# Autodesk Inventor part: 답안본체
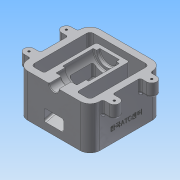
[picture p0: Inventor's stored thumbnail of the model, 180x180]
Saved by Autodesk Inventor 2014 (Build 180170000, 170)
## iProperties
Created: 2018-01
Part Number: 답안본체
Material: 알루미늄 6061
Document SubType Name: Modeling
Designer: NET
Density: 2.71 g/cm^3
Appearance: 알루미늄 - 평지
Mass: 998.903 g
Surface Area: 834.406 cm^2
Volume: 368.599 cm^3
Author: NET
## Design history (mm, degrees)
sketch "스케치1"
  geometry: L1 (55, -55)-(-55, -55); L2 (-55, -55)-(-55, 55); L3 (-55, 55)-(55, 55); L4 (55, 55)-(55, -55); L5 (55, -55)-(-55, 55); L6 (-55, -55)-(55, 55); 1 further point
  constraints: 12 end point, 2 midpoint, 2 parallel, 1 horizontal, 1 perpendicular
  dimensions: "d0" = 110 distance of L2.end L3.end; "d1" = 110 distance of L3.end L1.start
extrude "돌출1" new body sketch "스케치1" distance "d2" = 65; taper "d3" = 0 deg
sketch "스케치2"
  geometry: L1 (55, -55)-(55, 55) reference; L2 (55, 55)-(-55, 55) reference; L3 (45, -45)-(-45, -45); L4 (-45, -45)-(-45, 45); L5 (-45, 45)-(45, 45); L6 (45, 45)-(45, -45); L7 (45, -45)-(-45, 45); L8 (-45, -45)-(45, 45); 1 further point
  constraints: 12 end point, 2 midpoint, 2 parallel, 1 horizontal, 1 perpendicular
  dimensions: "d4" = 10 distance between parallel lines of L2 L5; "d5" = 10 distance between parallel lines of L1 L6
extrude "돌출2" cut sketch "스케치2" stored distance "d6" = 65; taper "d7" = 0 deg
sketch "스케치3"
  geometry: L1 (-55, -55)-(55, -55) reference; L2 (55, -55)-(55, 55) reference; L3 (-55, 55)-(-55, -55) reference; L4 (-65, -35.5)-(-55, -35.5); L5 (-65, -20.5)-(-55, -20.5); L6 (-65, 21.5)-(-55, 21.5); L7 (-65, 36.5)-(-55, 36.5); L8 (65, 36.5)-(55, 36.5); L9 (55, 55)-(55, -55) reference; L10 (65, 21.5)-(55, 21.5); L11 (65, -20.5)-(55, -20.5); L12 (65, -35.5)-(55, -35.5); A1 r 7.5 centre (-65, -28) between (-65, -20.5) and (-65, -35.5); A2 r 7.5 centre (-65, 29) between (-65, 36.5) and (-65, 21.5); A3 r 7.5 centre (65, -28) between (65, -35.5) and (65, -20.5); A4 r 7.5 centre (65, 29) between (65, 21.5) and (65, 36.5); 1 further point
  constraints: 16 end point, 8 point on circle, 8 point on line, 8 tangent, 6 perpendicular, 4 centre point, 3 equal radius, 2 parallel
  dimensions: "d8" = 57 distance of A2.centre A1.centre; "d9" = 27 distance from line of L1 A1.centre; "d10" = 27 distance from line of L1 A3.centre; "d11" = 57 distance of A4.centre A3.centre; "d12" = 10 distance from line of L2 A4.centre; "d13" = 10 distance from line of L2 A3.centre; "d14" = 15 diameter of A4; "d15" = 10 distance from line of L3 A2.centre; "d16" = 10 distance from line of L3 A1.centre
extrude "돌출3" join sketch "스케치3" distance "d17" = 20; taper "d18" = 0 deg
fillet "모깎기1" dims "d19" = 3
fillet "모깎기2" dims "d20" = 3
fillet "모깎기3" dims "d21" = 3
fillet "모깎기4" dims "d22" = 3
sketch "스케치4"
  geometry: A1 r 7.5 centre (65, -28) between (65, -35.5) and (65, -20.5) reference; A2 r 7.5 centre (65, 29) between (65, 21.5) and (65, 36.5) reference; A3 r 7.5 centre (-65, 29) between (-65, 36.5) and (-65, 21.5) reference; A4 r 7.5 centre (-65, -28) between (-65, -20.5) and (-65, -35.5) reference; 5 further points
  constraints: 4 coincident
hole "구멍1" sketch "스케치4" at (-65, 29), (65, 29), (65, -28), (-65, -28) diameter "d23" = 3.242; stored, may be unused: countersink angle "d27" = 90 deg, drill point angle "d29" = 118 deg; dims "d24" = 9, "d25" = 4, "d26" = 2, "d28" = 11
node "작업 평면1"
sketch "스케치5"
  geometry: L1 (110, 65)-(110, 0) reference; L2 (110, 0)-(100, 0) reference; L3 (100, 0)-(100, 65) reference; L4 (100, 65)-(110, 65) reference; L5 (0, 0)-(0, 65) reference; L6 (0, 65)-(10, 65) reference; L7 (10, 65)-(10, 0) reference; L8 (10, 0)-(0, 0) reference; L9 (10, 65)-(90, 65); L10 (90, 65)-(90, 30); L11 (90, 30)-(10, 8.564); L12 (10, 65)-(10, 8.564); L13 (16.5, 65)-(0, 65) reference; L14 (100, 0)-(10, 0) reference; 1 further point
  constraints: 8 end point, 2 perpendicular, 1 parallel, 1 point on line
  dimensions: "d30" = 30 distance from line of L14 L10.end; "d31" = 20 distance between parallel lines of L1 L10; "d32" = 105 deg angle of L7 L11
extrude "돌출4" join sketch "스케치5" stored distance "d33" = 50; taper "d34" = 0 deg
sketch "스케치6"
  geometry: L1 (-55, -55)-(55, -55) reference; L2 (55, 55)-(-55, 55) reference; L3 (0, -55)-(0, 55); L4 (-7.5, -55)-(-7.5, -36); L5 (-7.5, -36)-(-16, -36); L6 (-16, -36)-(-16, -22); L7 (-16, -22)-(-20, -22); L8 (-20, -22)-(-20, 25); L9 (-20, 25)-(-15, 25); L10 (-15, 25)-(-15, 30); L11 (-15, 30)-(0, 30); 1 further point
  constraints: 18 end point, 7 parallel, 2 midpoint, 2 point on line, 1 perpendicular
  dimensions: "d35" = 15 diameter of L4 L3; "d36" = 19 distance of L4.start L4.end; "d37" = 14 distance of L5.end L6.end; "d38" = 47 distance of L7.end L8.end; "d39" = 5 distance of L9.end L10.end; "d40" = 32 diameter of L6 L3; "d41" = 40 diameter of L8 L3; "d42" = 30 diameter of L10 L3
revolve "회전1" sketch "스케치6" stored, may be unused: angle "d43" = 90 deg
sketch "스케치7"
  geometry: L1 (-20, -22)-(-20, 25) reference; L2 (-20, 25)-(-15, 25) reference; L3 (-15, -17)-(15, -17); L4 (15, -17)-(15, 20); L5 (15, 20)-(-15, 20); L6 (-15, 20)-(-15, -17); 1 further point
  constraints: 8 end point, 2 parallel, 1 horizontal, 1 perpendicular
  dimensions: "d44" = 30 distance between parallel lines of L4 L6; "d45" = 37 distance of L5.end L3.start; "d46" = 5 distance between parallel lines of L2 L5; "d47" = 5 distance between parallel lines of L1 L6
extrude "돌출5" cut sketch "스케치7" distance "d48" = 30; taper "d49" = 0 deg
sketch "스케치8"
  geometry: L1 (30, 50)-(30, 65) reference; L2 (30, 65)-(35, 65) reference; L3 (35, 65)-(35, 30) reference; L4 (35, 30)-(-45, 8.564) reference; L5 (-45, 8.564)-(-45, 0) reference; L6 (-45, 0)-(-55, 0) reference; L7 (-55, 0)-(-55, 57.5) reference; L8 (-55, 57.5)-(-36, 57.5) reference; L9 (-36, 57.5)-(-36, 49) reference; L10 (-36, 49)-(-22, 49) reference; L11 (-22, 49)-(-22, 45) reference; L12 (-22, 45)-(-17, 45) reference; L13 (-17, 45)-(-17, 35) reference; L14 (-17, 35)-(20, 35) reference; L15 (20, 35)-(20, 45) reference; L16 (20, 45)-(25, 45) reference; L17 (25, 45)-(25, 50) reference; L18 (25, 50)-(30, 50) reference; L19 (45, 65)-(55, 65) reference; L20 (55, 65)-(55, 0) reference; L21 (55, 0)-(45, 0) reference; L22 (45, 0)-(45, 65) reference; L23 (-55, 11.061)-(20, 31.157); L24 (20, 31.157)-(20, 35); L25 (-55, 29.061)-(-17, 39.243); L26 (-17, 39.243)-(-17, 35); 1 further point
  constraints: 8 end point, 4 parallel, 2 point on line
  dimensions: "d50" = 5 distance between parallel lines of L4 L23; "d51" = 18 distance of L23.start L25.start
extrude "돌출6" cut sketch "스케치8" stored distance "d52" = 30; taper "d53" = 0 deg
fillet "모깎기5" dims "d54" = 1
chamfer "모따기1" distance "d55" = 1; stored, may be unused: second distance "d56" = 2, angle "d57" = 45 deg
fillet "모깎기6" dims "d58" = 3
fillet "모깎기7" dims "d59" = 3
fillet "모깎기8" dims "d60" = 3
fillet "모깎기9" dims "d61" = 3
fillet "모깎기10" dims "d62" = 3
fillet "모깎기11" dims "d63" = 3
fillet "모깎기12" dims "d64" = 15
fillet "모깎기13" dims "d65" = 5
sketch "스케치9"
  geometry: L1 (65, 57.5)-(65, -22.5) reference; L2 (0, -37.5)-(65, -37.5) reference; 2 further points
  constraints: 1 other
  dimensions: "d66" = 55 distance from line of point (45, 17.5) L2; "d67" = 20 distance from line of L1 point (45, 17.5)
feature "엠보싱1" sketch "스케치9" dims "d0" = 110, "d1" = 110, "d68" = 0.5, "d69" = 0
node "솔리드1"
node "절단 모서리 투영1"
node "절단 모서리 투영2"
